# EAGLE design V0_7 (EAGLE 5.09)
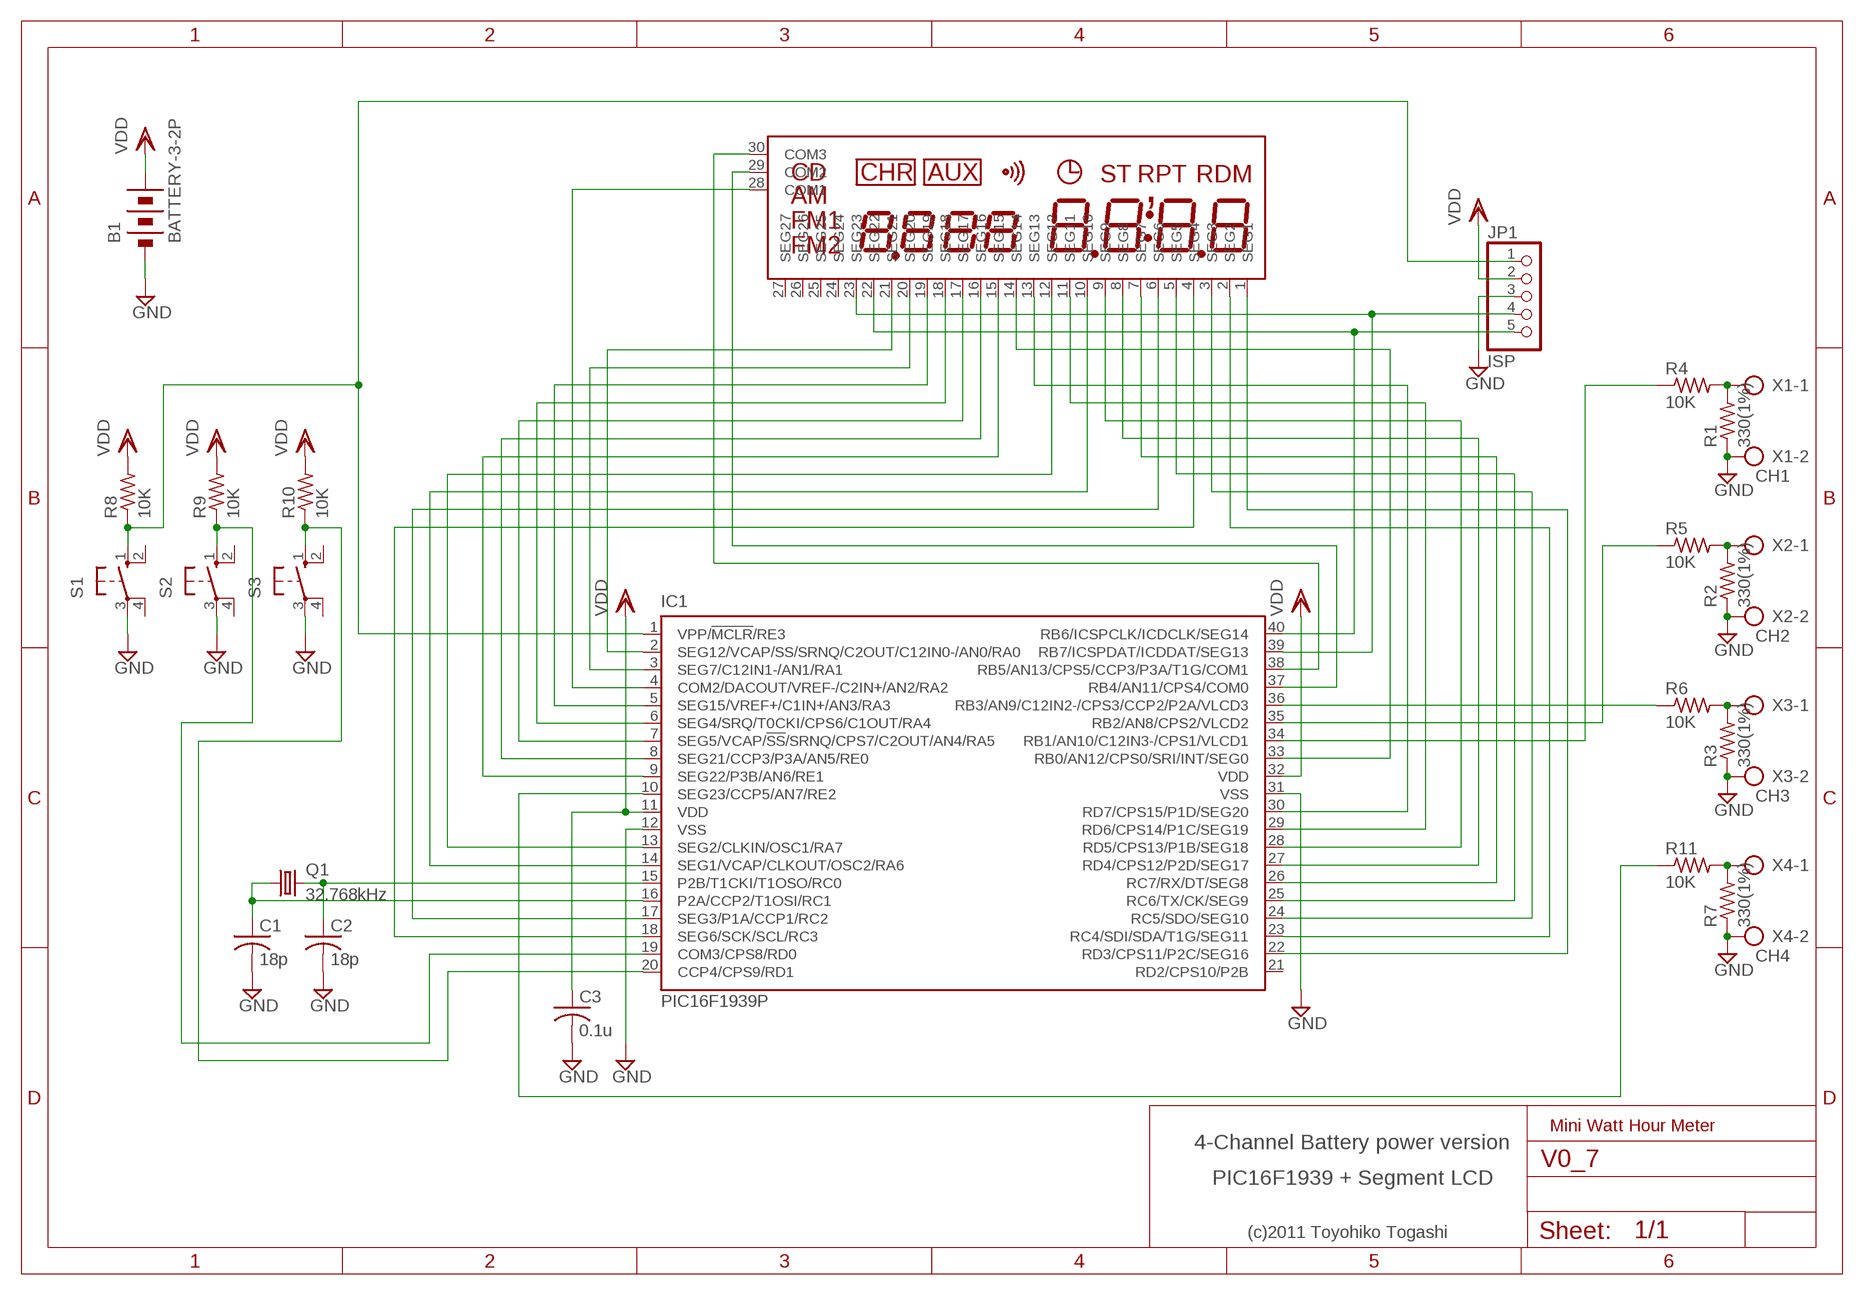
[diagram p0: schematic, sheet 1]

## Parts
B1  BATTERY-3-2P  [CONN-2P]
C1  18p  C-US025-024X044  [C025-024X044]
C2  18p  C-US025-024X044  [C025-024X044]
C3  0.1u  C-US025-024X044  [C025-024X044]
IC1  PIC16F1939P  [DIL40]
JP1  ISP  PINHD-1X5  [1X05]
LCD1  LCD-30P-AITENDO  [LCD-30P-AITENDO]
Q1  32.768kHz  CRYSTALTC38H  [TC38H]
R1  330(1%)  R-US_0204/7  [0204/7]
R2  330(1%)  R-US_0204/7  [0204/7]
R3  330(1%)  R-US_0204/7  [0204/7]
R4  10K  R-US_0204/5  [0204/5]
R5  10K  R-US_0204/5  [0204/5]
R6  10K  R-US_0204/5  [0204/5]
R7  330(1%)  R-US_0204/7  [0204/7]
R8  10K  R-US_0204/5  [0204/5]
R9  10K  R-US_0204/5  [0204/5]
R10  10K  R-US_0204/5  [0204/5]
R11  10K  R-US_0204/5  [0204/5]
S1  10-XX  [B3F-10XX]
S2  10-XX  [B3F-10XX]
S3  10-XX  [B3F-10XX]
X1  CH1  AK300/2  [AK300/2]
X2  CH2  AK300/2  [AK300/2]
X3  CH3  AK300/2  [AK300/2]
X4  CH4  AK300/2  [AK300/2]

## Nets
GND: B1.P$2(MINUS) C1.2 C2.2 C3.2 IC1.12(VSS) IC1.31(VSS) JP1.3 R1.1 R2.1 R3.1 R7.1 S1.3(P) S2.3(P) S3.3(P) X1.2 X2.2 X3.2 X4.2
N$1: IC1.37(RB4/AN11/CPS4/COM0) LCD1.29(COM2)
N$2: IC1.38(RB5/AN13/CPS5/CCP3/P3A/T1G/COM1) LCD1.30(COM3)
N$3: IC1.40(RB6/ICSPCLK/ICDCLK/SEG14) JP1.5 LCD1.22(SEG22)
N$4: IC1.2(SEG12/VCAP/SS/SRNQ/C2OUT/C12IN0-/AN0/RA0) LCD1.21(SEG21)
N$5: IC1.14(SEG1/VCAP/CLKOUT/OSC2/RA6) LCD1.10(SEG10)
N$6: IC1.13(SEG2/CLKIN/OSC1/RA7) LCD1.12(SEG12)
N$7: IC1.17(SEG3/P1A/CCP1/RC2) LCD1.6(SEG6)
N$8: IC1.6(SEG4/SRQ/T0CKI/CPS6/C1OUT/RA4) LCD1.18(SEG18)
N$9: IC1.7(SEG5/VCAP/!SS!/SRNQ/CPS7/C2OUT/AN4/RA5) LCD1.17(SEG17)
N$10: IC1.18(SEG6/SCK/SCL/RC3) LCD1.4(SEG4)
N$11: IC1.22(RD3/CPS11/P2C/SEG16) LCD1.1(SEG1)
N$12: IC1.26(RC7/RX/DT/SEG8) LCD1.7(SEG7)
N$13: IC1.25(RC6/TX/CK/SEG9) LCD1.5(SEG5)
N$14: IC1.24(RC5/SDO/SEG10) LCD1.3(SEG3)
N$15: IC1.23(RC4/SDI/SDA/T1G/SEG11) LCD1.2(SEG2)
N$16: IC1.1(VPP/!MCLR!/RE3) JP1.1 R8.1 S1.1(S)
N$17: R7.2 R11.2 X4.1
N$18: IC1.39(RB7/ICSPDAT/ICDDAT/SEG13) JP1.4 LCD1.23(SEG23)
N$19: IC1.10(SEG23/CCP5/AN7/RE2) R11.1
N$21: IC1.27(RD4/CPS12/P2D/SEG17) LCD1.8(SEG8)
N$22: IC1.28(RD5/CPS13/P1B/SEG18) LCD1.9(SEG9)
N$24: IC1.19(COM3/CPS8/RD0) R9.1 S2.1(S)
N$25: IC1.4(COM2/DACOUT/VREF-/C2IN+/AN2/RA2) LCD1.28(COM1)
N$26: IC1.29(RD6/CPS14/P1C/SEG19) LCD1.11(SEG11)
N$28: IC1.8(SEG21/CCP3/P3A/AN5/RE0) LCD1.16(SEG16)
N$29: IC1.9(SEG22/P3B/AN6/RE1) LCD1.15(SEG15)
N$31: C2.1 IC1.15(P2B/T1CKI/T1OSO/RC0) Q1.2
N$32: C1.1 IC1.16(P2A/CCP2/T1OSI/RC1) Q1.1
N$33: IC1.34(RB1/AN10/C12IN3-/CPS1/VLCD1) R4.1
N$36: IC1.20(CCP4/CPS9/RD1) R10.1 S3.1(S)
N$37: R1.2 R4.2 X1.1
N$38: IC1.33(RB0/AN12/CPS0/SRI/INT/SEG0) LCD1.14(SEG14)
N$39: R2.2 R5.2 X2.1
N$40: IC1.35(RB2/AN8/CPS2/VLCD2) R5.1
N$41: R3.2 R6.2 X3.1
N$42: IC1.36(RB3/AN9/C12IN2-/CPS3/CCP2/P2A/VLCD3) R6.1
N$45: IC1.30(RD7/CPS15/P1D/SEG20) LCD1.13(SEG13)
N$47: IC1.3(SEG7/C12IN1-/AN1/RA1) LCD1.20(SEG20)
N$51: IC1.5(SEG15/VREF+/C1IN+/AN3/RA3) LCD1.19(SEG19)
VDD: B1.P$1(PLUS) C3.1 IC1.11(VDD) IC1.32(VDD) JP1.2 R8.2 R9.2 R10.2
Unconnected: IC1.21(RD2/CPS10/P2B) LCD1.24(SEG24) LCD1.25(SEG25) LCD1.26(SEG26) LCD1.27(SEG27) S1.2(S1) S1.4(P1) S2.2(S1) S2.4(P1) S3.2(S1) S3.4(P1)

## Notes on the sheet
- Mini Watt Hour Meter
- 4-Channel Battery power version
- PIC16F1939 + Segment LCD
- (c)2011 Toyohiko Togashi

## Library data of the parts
B1 = TOG:BATTERY-3: Battery 3cell
C1-C3 = rcl:C-US: CAPACITOR, American symbol
IC1 = microchip:PIC16F193*?: Flash-Based, 8-Bit CMOS Microcontrollers wtih LCD Driver and nanoWatt XLP Technology Auto generated by make-symbol-device-package-bsdl.ulp Rev. 33 Source: http://ww1.microchip.com/downloads/en/DeviceDoc/41364D.pdf
JP1 = pinhead:PINHD-1X5: PIN HEADER
LCD1 = TOG:LCD-30P-AITENDO
Q1 = crystal:CRYSTAL: CRYSTAL
R1-R11 = rcl:R-US_: RESISTOR, American symbol
S1-S3 = switch-omron:10-XX: OMRON SWITCH
X1-X4 = con-ptr500:AK300/2: CONNECTOR

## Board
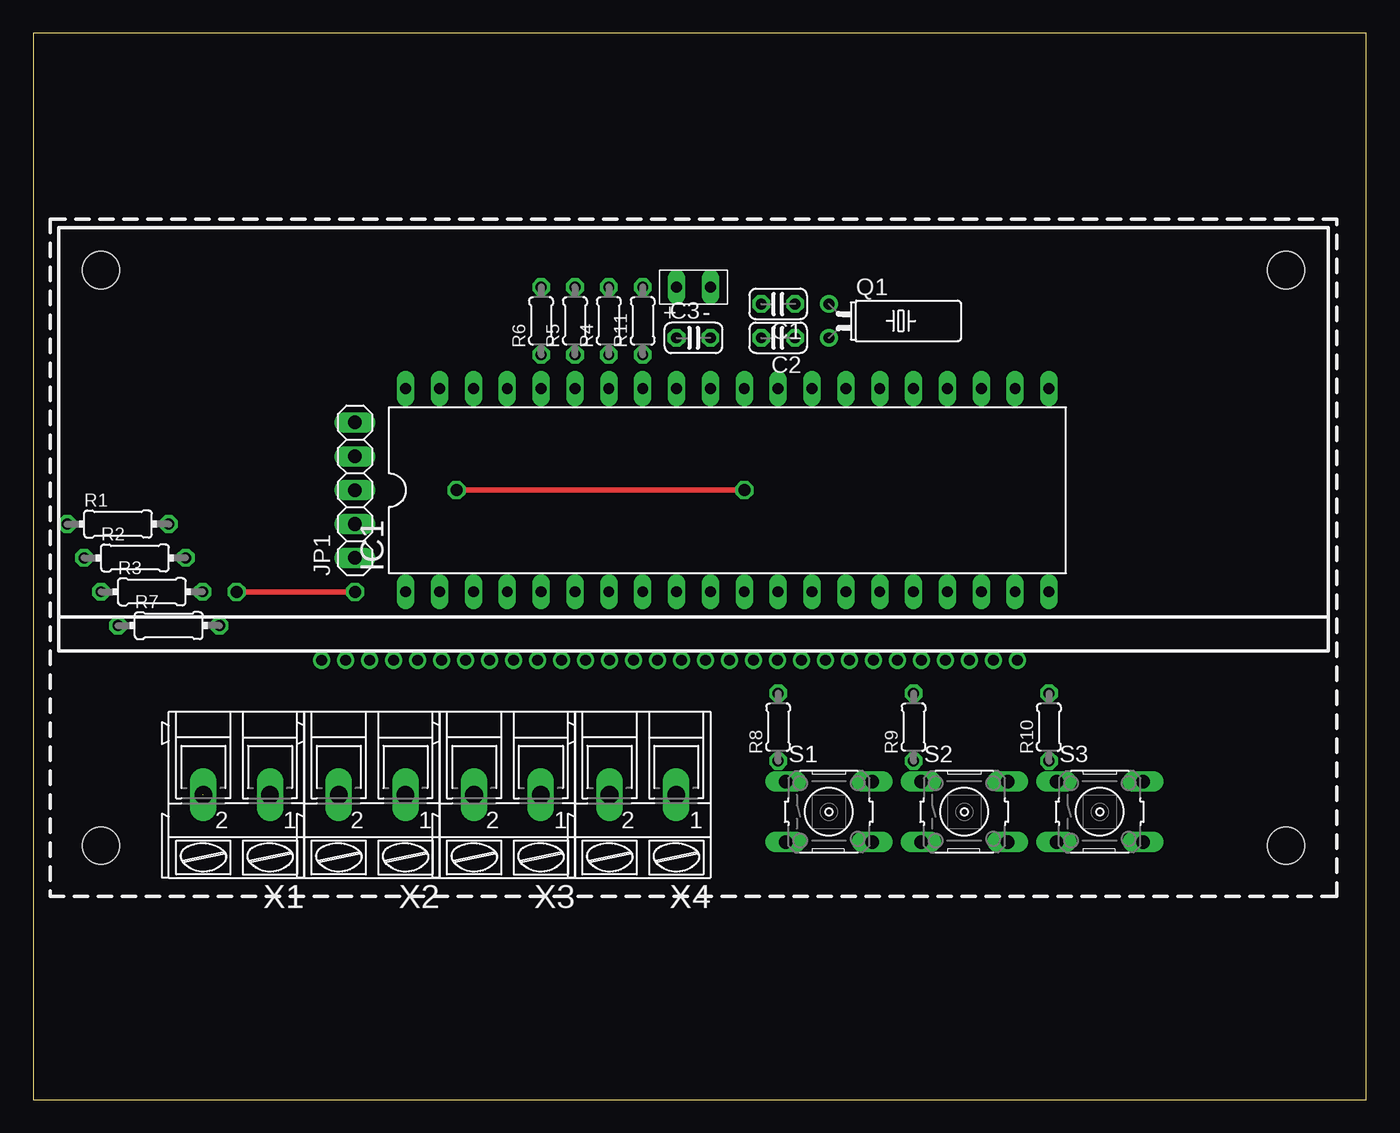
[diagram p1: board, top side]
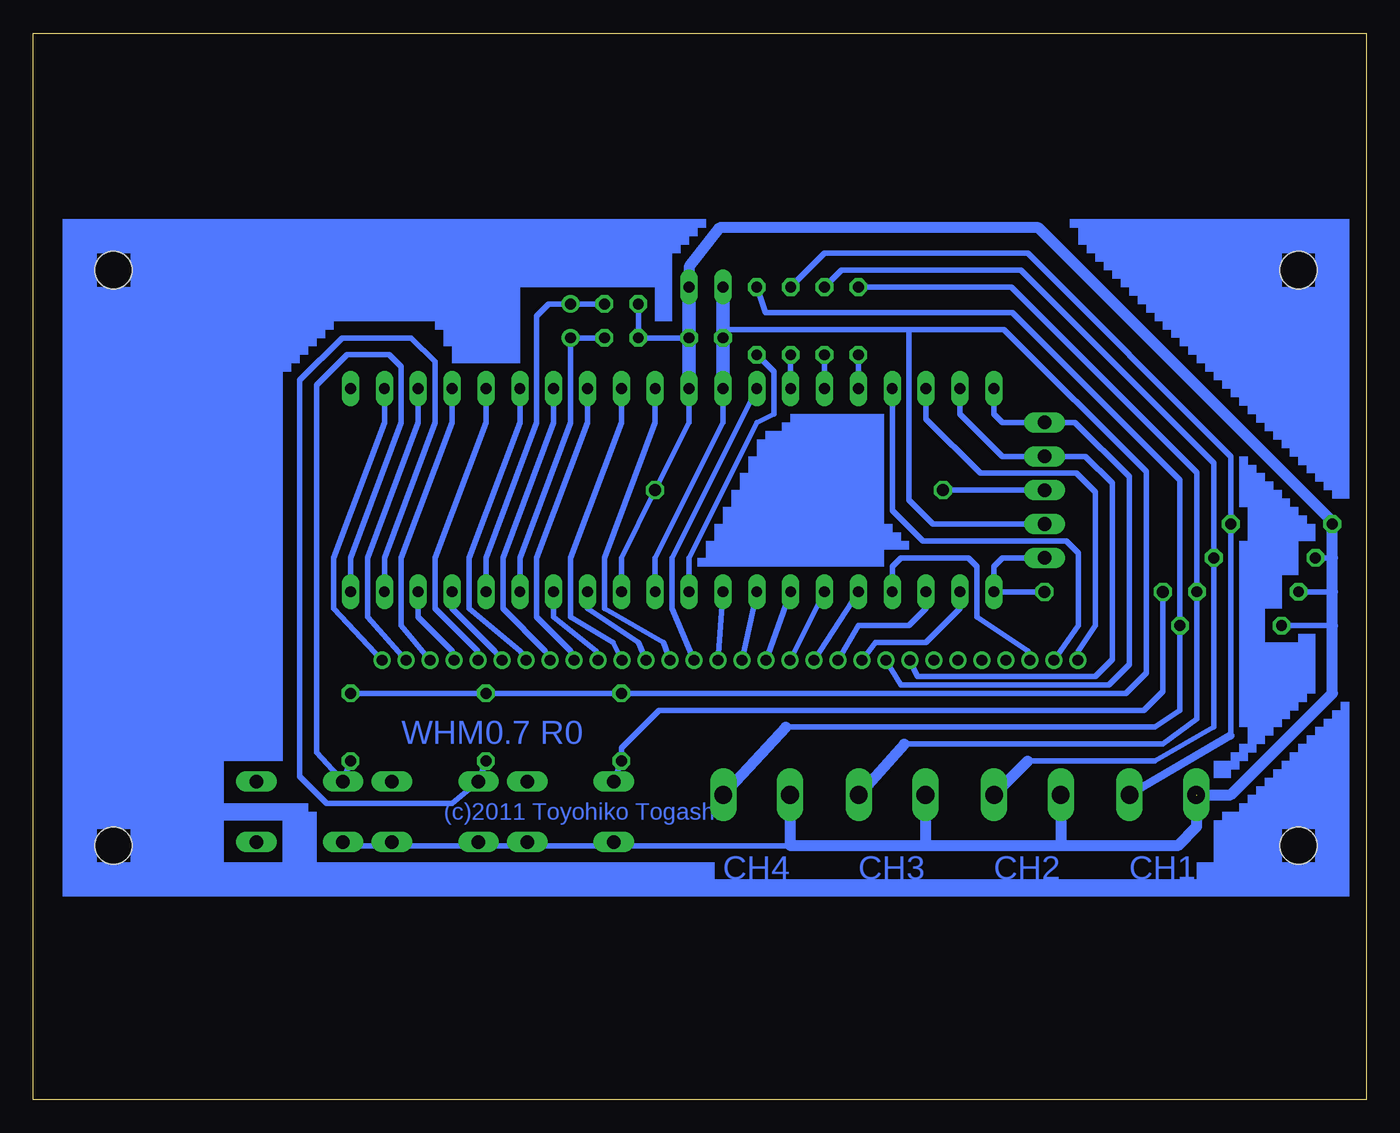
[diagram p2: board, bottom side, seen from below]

Size 100 x 80 mm. Coordinates in mm from the lower left corner, seen from the top.
Outline: 0,0 100,0 100,80 0,80 0,0
Copper layers (1*16): Top 0.035mm / dielectric 1.5mm / Bottom 0.035mm
Design rules "default": minimum track width 10mil, minimum drill 24mil, track to track 8mil, track to pad 8mil, pad to pad 8mil, via to via 8mil, smd to smd 8mil, copper to edge 40mil, drill to drill 8mil, minimum pad ring 10mil, minimum via ring 8mil, stop-mask expansion 4mil, vias tented up to drill 0mil, thermal gap 10mil
Holes 2.8 mm at 5.08,19.05 93.98,19.05 93.98,62.23 5.08,62.23

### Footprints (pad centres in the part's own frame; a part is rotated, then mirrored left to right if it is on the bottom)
CONN-2P = drill 0.8 long: P$1 1.27,0; P$2 -1.27,0
C025-024X044 = drill 0.813 octagon: 1 -1.27,0; 2 1.27,0
DIL40 = drill 0.813 long: 1 -24.13,-7.62; 2 -21.59,-7.62; 3 -19.05,-7.62; 4 -16.51,-7.62; 5 -13.97,-7.62; 6 -11.43,-7.62; 7 -8.89,-7.62; 8 -6.35,-7.62; 9 -3.81,-7.62; 10 -1.27,-7.62; 11 1.27,-7.62; 12 3.81,-7.62; 13 6.35,-7.62; 14 8.89,-7.62; 15 11.43,-7.62; 16 13.97,-7.62; 17 16.51,-7.62; 18 19.05,-7.62; 19 21.59,-7.62; 20 24.13,-7.62; 21 24.13,7.62; 22 21.59,7.62; 23 19.05,7.62; 24 16.51,7.62; 25 13.97,7.62; 26 11.43,7.62; 27 8.89,7.62; 28 6.35,7.62; 29 3.81,7.62; 30 1.27,7.62; 31 -1.27,7.62; 32 -3.81,7.62; 33 -6.35,7.62; 34 -8.89,7.62; 35 -11.43,7.62; 36 -13.97,7.62; 37 -16.51,7.62; 38 -19.05,7.62; 39 -21.59,7.62; 40 -24.13,7.62
1X05 = drill 1.016 long: 1 -5.08,0; 2 -2.54,0; 3 0,0; 4 2.54,0; 5 5.08,0
LCD-30P-AITENDO = drill 0.8 round: 1 24.3,-15.3; 2 22.5,-15.3; 3 20.7,-15.3; 4 18.9,-15.3; 5 17.1,-15.3; 6 15.3,-15.3; 7 13.5,-15.3; 8 11.7,-15.3; 9 9.9,-15.3; 10 8.1,-15.3; 11 6.3,-15.3; 12 4.5,-15.3; 13 2.7,-15.3; 14 0.9,-15.3; 15 -0.9,-15.3; 16 -2.7,-15.3; 17 -4.5,-15.3; 18 -6.3,-15.3; 19 -8.1,-15.3; 20 -9.9,-15.3; 21 -11.7,-15.3; 22 -13.5,-15.3; 23 -15.3,-15.3; 24 -17.1,-15.3; 25 -18.9,-15.3; 26 -20.7,-15.3; 27 -22.5,-15.3; 28 -24.3,-15.3; 29 -26.1,-15.3; 30 -27.9,-15.3
TC38H = drill 0.813 round: 1 -1.27,0; 2 1.27,0
0204/7 = drill 0.813 octagon: 1 -3.81,0; 2 3.81,0
0204/5 = drill 0.813 octagon: 1 -2.54,0; 2 2.54,0
B3F-10XX = drill 1.016 long: 1 -3.251,2.261; 2 3.251,2.261; 3 -3.251,-2.261; 4 3.251,-2.261
AK300/2 = drill 1.321 long: 1 -2.515,0; 2 2.489,0

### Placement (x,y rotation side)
B1  49.53,60.96 180 top
C1  55.88,59.69 180 top
C2  55.88,57.15 180 top
C3  49.53,57.15 0 top
IC1  52.07,45.72 0 top
JP1  24.13,45.72 90 top
LCD1  49.53,48.26 0 top
Q1  59.69,58.42 270 top
R1  6.35,43.18 0 top
R2  7.62,40.64 0 top
R3  8.89,38.1 0 top
R4  43.18,58.42 90 top
R5  40.64,58.42 90 top
R6  38.1,58.42 90 top
R7  10.16,35.56 0 top
R8  55.88,27.94 90 top
R9  66.04,27.94 90 top
R10  76.2,27.94 90 top
R11  45.72,58.42 90 top
S1  59.69,21.59 0 top
S2  69.85,21.59 0 top
S3  80.01,21.59 0 top
X1  15.24,22.86 180 top
X2  25.4,22.86 180 top
X3  35.56,22.86 180 top
X4  45.72,22.86 180 top

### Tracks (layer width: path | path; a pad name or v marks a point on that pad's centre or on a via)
GND  (via drill 0.9)  (1 unrouted)
  Top 0.406: v53.34,45.72 v31.75,45.72
  Bottom 0.406: IC1.31 50.8,50.8 v53.34,45.72 55.88,40.64 IC1.12 | C1.2 C2.2 C3.2 | 12.7,22.86 12.7,24.13 | 43.18,19.05 55.88,19.05 | 55.88,19.05 66.04,19.05 | 66.04,19.05 76.2,19.05 S3.3 | 66.04,19.05 S2.3 | 55.88,19.05 S1.3 | v31.75,45.72 JP1.3 | 2.54,35.56 R7.1 | 2.54,38.1 R3.1 | 2.54,40.64 R2.1
  Bottom 0.813: 22.86,19.05 14.14,19.05 12.72,20.49 X1.2 10.16,22.86 2.54,30.48 2.54,35.56 2.54,38.1 2.54,40.64 R1.1 2.54,43.36 24.58,65.41 48.51,65.41 50.8,62.48 B1.P$2 | 22.86,19.05 33.02,19.05 | 33.02,19.05 43.18,19.05 X4.2 | 22.86,19.05 X2.2 | 33.02,19.05 X3.2
  Bottom 1.016: IC1.31 C3.2 B1.P$2
N$1
  Bottom 0.406: LCD1.29 21.59,35.56 21.59,41.01 22.49,41.91 33.27,41.91 35.56,44.2 IC1.37
N$2
  Bottom 0.406: IC1.38 33.02,51.06 28.95,46.99 21.74,46.99 20.32,45.57 20.32,35.56 21.59,33.66 LCD1.30
N$3
  Bottom 0.406: IC1.40 27.94,51.44 27.3,50.8 JP1.5 21.85,50.8 17.78,46.73 17.78,32.65 19.31,31.11 34.92,31.11 LCD1.22
N$4
  Bottom 0.406: IC1.2 30.48,36.83 33.02,34.29 36.83,34.29 LCD1.21
N$5
  Bottom 0.406: LCD1.10 57.78,33.66 60.96,36.2 IC1.14
N$6
  Bottom 0.406: LCD1.12 54.61,34.29 58.42,36.83 IC1.13
N$7
  Bottom 0.406: LCD1.6 65.41,33.66 68.58,36.83 IC1.17
N$8
  Bottom 0.406: IC1.6 LCD1.18
N$9
  Bottom 0.406: IC1.7 LCD1.17
N$10
  Bottom 0.406: LCD1.4 68.58,33.66 71.12,36.2 IC1.18
N$11
  Bottom 0.406: IC1.22 73.66,50.8 77.47,40.64 77.47,36.83 LCD1.1
N$12
  Bottom 0.406: LCD1.7 63.5,33.66 67.31,36.83 67.31,40.64 63.5,50.8 IC1.26
N$13
  Bottom 0.406: LCD1.5 66.67,33.66 69.85,36.83 69.85,40.64 66.04,50.8 IC1.25
N$14
  Bottom 0.406: LCD1.3 72.39,35.56 72.39,40.64 68.58,50.8 IC1.24
N$15
  Bottom 0.406: LCD1.2 74.93,36.2 74.93,40.64 71.12,50.8 IC1.23
N$16  (via drill 0.9)
  Top 0.406: v15.24,38.1 v24.13,38.1
  Bottom 0.406: S1.1 R8.1 55.88,26.37 53.04,29.21 16.66,29.21 15.24,30.63 v15.24,38.1 | v24.13,38.1 IC1.1 27.94,40.01 27.3,40.64 JP1.1
N$17
  Bottom 0.406: 43.55,27.94 15.88,27.94 13.97,29.21 R7.2 13.97,46.48 26.55,59.05 45.09,59.05 R11.2 | 48.26,22.86 X4.1
  Bottom 0.813: 43.55,27.94 48.26,22.86
N$18
  Bottom 0.406: IC1.39 30.48,51.44 27.3,48.26 JP1.4 21.06,48.26 19.05,46.25 19.05,33.02 20.32,31.75 33.66,31.75 LCD1.23
N$19
  Bottom 0.406: R11.1 44.45,54.61 44.45,51.44 45.72,50.8 50.8,40.64 IC1.10
N$21
  Bottom 0.406: LCD1.8 61.59,33.66 64.77,36.83 64.77,40.64 60.96,50.8 IC1.27
N$22
  Bottom 0.406: LCD1.9 59.69,33.66 62.23,36.2 62.23,40.64 58.42,50.8 IC1.28
N$24
  Bottom 0.406: R9.1 S2.1 68.58,22.23 78,22.23 80.01,24.23 80.01,53.98 76.83,57.15 71.65,57.15 69.85,55.35 69.85,50.8 73.66,40.64 IC1.19
N$25
  Bottom 0.406: LCD1.28 25.4,33.66 29.21,36.2 29.21,40.01 29.84,40.64 34.92,40.64 35.56,40.01 IC1.4
N$26
  Bottom 0.406: LCD1.11 56.52,34.29 59.69,36.2 59.69,40.64 55.88,50.8 IC1.29
N$28
  Bottom 0.406: IC1.8 LCD1.16
N$29
  Bottom 0.406: IC1.9 LCD1.15
N$31
  Bottom 0.406: C2.1 Q1.2 59.69,50.8 63.5,40.64 IC1.15
N$32
  Bottom 0.406: C1.1 Q1.1 61.33,59.69 62.23,58.79 62.23,50.8 66.04,40.64 IC1.16
N$33
  Bottom 0.406: IC1.34 R4.1
N$36
  Bottom 0.406: R10.1 S3.1 78.74,26.04 78.74,53.59 76.45,55.88 73.29,55.88 72.39,54.98 72.39,50.8 76.2,40.64 IC1.20
N$37
  Bottom 0.406: 10.16,27.3 R1.2 10.16,48.26 25.4,63.5 40.64,63.5 R4.2
  Bottom 0.61: 10.16,27.3 X1.1
N$38
  Bottom 0.406: LCD1.14 52.07,36.83 52.07,40.64 IC1.33
N$39
  Bottom 0.406: 25.4,25.4 15.88,25.4 11.43,27.94 R2.2 11.43,47.75 25.91,62.23 39.37,62.23 R5.2
  Bottom 0.813: 25.4,25.4 X2.1
N$40
  Bottom 0.406: IC1.35 R5.1
N$41
  Bottom 0.406: 34.66,26.67 15.24,26.67 12.7,28.57 R3.2 12.7,47.03 26.63,60.96 R6.2
  Bottom 0.813: 34.66,26.67 X3.1
N$42
  Bottom 0.406: IC1.36 R6.1
N$45
  Bottom 0.406: LCD1.13 52.7,34.29 57.15,36.83 57.15,40.64 53.34,50.8 IC1.30
N$47
  Bottom 0.406: IC1.3 33.02,36.83 34.29,35.56 38.1,35.56 LCD1.20
N$51
  Bottom 0.406: IC1.5 LCD1.19
VDD
  Bottom 0.406: IC1.32 48.26,50.8 53.34,40.64 IC1.11 | R10.2 R9.2 R8.2 18.04,30.48 16.51,32.01 16.51,47.11 27.18,57.78 34.29,57.78 | JP1.2 32.49,43.18 34.29,44.98 34.29,57.78 | 34.29,57.78 48.26,57.78
  Bottom 0.813: B1.P$1 48.26,61.33
  Bottom 1.016: IC1.32 C3.1 48.26,57.78 B1.P$1
(copper drawn outside any net)
  shapes: Bottom area x113

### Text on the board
Bottom: WHM0.7 R0 | (c)2011 Toyohiko Togashi | CH1 | CH2 | CH3 | CH4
